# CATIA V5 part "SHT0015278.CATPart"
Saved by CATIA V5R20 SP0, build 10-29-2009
Part number: Part60
Source: Unknown
Bounding box of the stored display mesh (mm): x 0 to 1473.999, y -744.973 to 0, z 0 to 84
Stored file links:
  E:\吉利商用车G3\10 2D\手动\钣金单件图纸\SHT0015278-高配底支架左边板\SHT0015278.CATPart
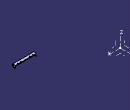
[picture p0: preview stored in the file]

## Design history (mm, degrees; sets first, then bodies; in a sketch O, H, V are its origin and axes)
Set1
  AxisSystem1 "AXIS2_PLACEMENT_3D #1659": origin (0, 0, 0), X (1, 0, 0), Y (0, 1, 0), Z (0, 0, 1)
Body1 "interface-2.2.1\\几何体.38" (main body)
  Solid1: solid without history
Body2 "680.2\\interface-2.2.1\\几何体.38"
  Solid2: solid without history
Body3 "680.2\\interface-2.2.1\\几何体.40"
  Solid3: solid without history
  RemoveFace1: RemoveFaces (face of Solid3; face of Solid3; face of Solid3)
  Thickness1: Thickness -15, Face face of Solid3
  Fillet1: radius 3, on edge [face of Solid3 | face of Solid3] (x2)
  Fillet2: radius 4, on edge [face of Solid3 | face of Solid3]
